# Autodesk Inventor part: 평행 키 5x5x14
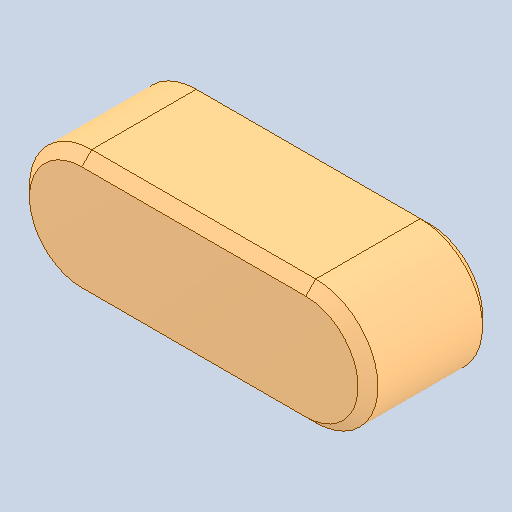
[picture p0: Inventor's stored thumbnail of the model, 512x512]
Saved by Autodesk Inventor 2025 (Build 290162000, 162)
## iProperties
Created: 2026-07
Part Number: 평행 키 5x5x14
Material: 강철, 연강
Document SubType Name: Modeling
Designer: KDI
Density: 7.86 g/cm^3
Appearance: 기본값
Author: jhkim
Revision Number: 1
Sending System: Autodesk Inventor 2027
Preprocessor: ST-DEVELOPER v20.1
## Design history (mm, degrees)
feature "솔리드1"
node "솔리드2"
